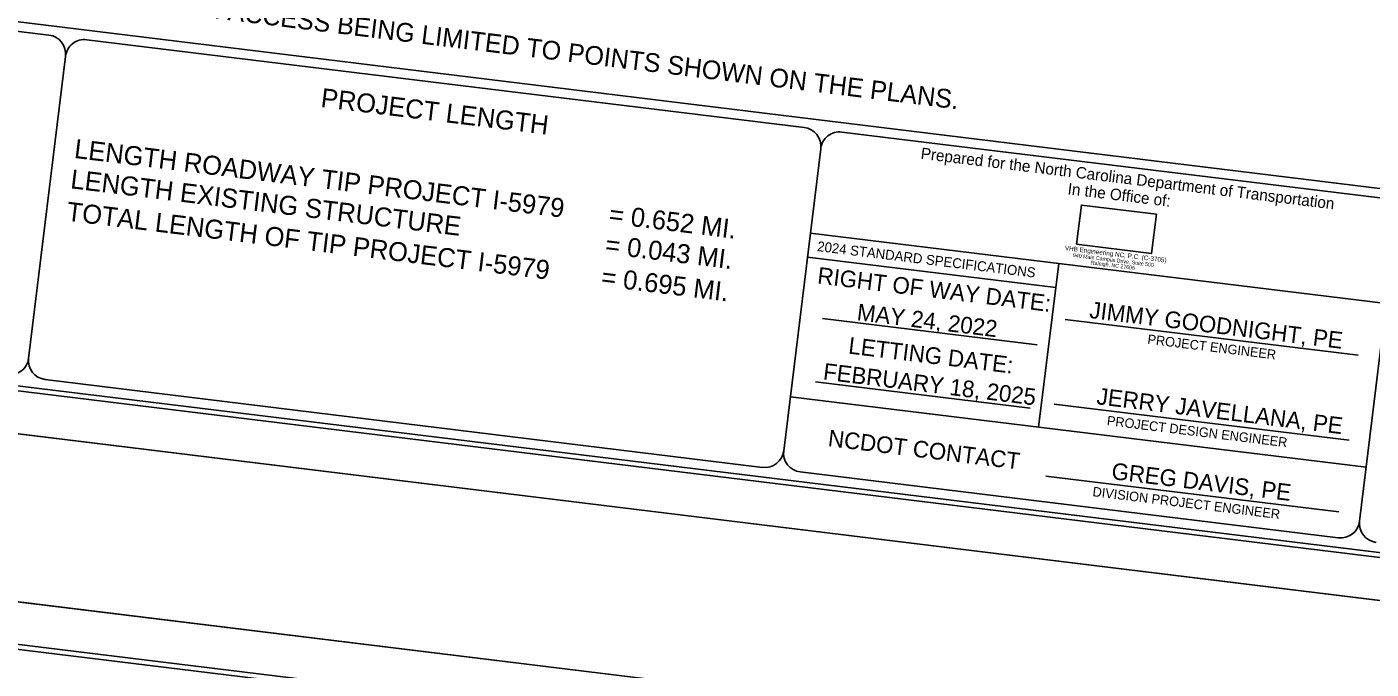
# Model space of a CAD drawing. Extents: x 1756435 to 1766932, y 416863 to 426859.
# Drawn here: x 1761555 to 1764409, y 421675 to 423038 of the extents above; entities that cross this region are included whole.
import ezdxf

# ---------------------------------------------------------------- set-up
doc = ezdxf.new("R2010")
doc.units = 0
for name, color, linetype in [('Default', 7, 'Continuous'), ('Old_Level_38', 7, 'Continuous'), ('Scratch_Level_2', 7, 'Continuous'), ('Sheet Cutting Line CELL', 7, 'Continuous'), ('Sheet Data Field CELL', 7, 'Continuous'), ('Sheet Plot Border Inside CELL', 7, 'Continuous'), ('Sheet Plot Border Outside CELL', 7, 'Continuous'), ('Sheet Symbology CELL', 7, 'Continuous'), ('Sheet Title CELL', 7, 'Continuous')]:
    doc.layers.add(name, color=color, linetype=linetype)

msp = doc.modelspace()

# ---------------------------------------------------------------- linework, layer by layer
at = {"layer": 'Default'}
msp.add_lwpolyline([(1763784, 422576.7), (1763943.2, 422557.2), (1763953.4, 422640.4), (1763794.2, 422659.9)], close=True, dxfattribs=at)
at = {"layer": 'Scratch_Level_2'}
msp.add_lwpolyline([(1759243.8, 422098.1), (1765929.9, 421280), (1765395.5, 416912.5), (1758709.3, 417730.7)], close=True, dxfattribs=at)
at = {"layer": 'Sheet Cutting Line CELL'}
for p, q in [((1759286.8, 422449.7), (1766036.5, 421623.8)), ((1765993.4, 421272.2), (1759243.8, 422098.1)), ((1765929.9, 421280), (1759243.8, 422098.1))]:
    msp.add_line(p, q, dxfattribs=at)
at = {"layer": 'Sheet Plot Border Inside CELL'}
for points in [[(1759349.9, 422533.3), (1766029.4, 421715.9), (1766546.9, 425944.9), (1759867.4, 426762.2)], [(1758771.9, 417813.5), (1765388.5, 417003.9), (1765901.1, 421193), (1759284.5, 422002.7)]]:
    msp.add_lwpolyline(points, close=True, dxfattribs=at)
at = {"layer": 'Sheet Plot Border Outside CELL'}
for points in [[(1766576, 426032.6), (1759826.3, 426858.6), (1759286.8, 422449.7), (1766036.5, 421623.8)], [(1758709.3, 417730.7), (1765395.5, 416912.5), (1765929.9, 421280), (1759243.8, 422098.1)]]:
    msp.add_lwpolyline(points, close=True, dxfattribs=at)
at = {"layer": 'Sheet Symbology CELL'}
msp.add_lwpolyline([(1765850.3, 421189), (1759894.7, 421917.7), (1759385, 417752.9), (1765340.6, 417024.1)], close=True, dxfattribs=at)
at = {"layer": 'Sheet Title CELL'}
for p, q in [((1760322.1, 423197.7), (1766013.7, 422501.2)), ((1761021.1, 423091.8), (1761602.3, 423020.7)), ((1761682.4, 423010.8), (1763205.5, 422824.5)), ((1761637.5, 422975.7), (1761559, 422334.4)), ((1763285.7, 422814.9), (1764428, 422675.1)), ((1763240.7, 422779.5), (1763162.2, 422138.2)), ((1764384.7, 421988.6), (1764463.2, 422629.9)), ((1764441.3, 422450.7), (1763218.8, 422600.3)), ((1763739.8, 422484.7), (1763212.5, 422549.2)), ((1763746.1, 422535.8), (1763703.5, 422188.3)), ((1763587.9, 422503.3), (1763587.9, 422503.3)), ((1763700.6, 422363.5), (1763244.6, 422419.3)), ((1763759.6, 422417.3), (1764381.5, 422341.1)), ((1763472.5, 422391.4), (1763472.5, 422391.4)), ((1763685.7, 422228.8), (1763229.8, 422284.6)), ((1764398.7, 422103.2), (1763176.3, 422252.9)), ((1763736.2, 422237.1), (1764362.4, 422160.5)), ((1763718.9, 422084.7), (1764340.8, 422008.6))]:
    msp.add_line(p, q, dxfattribs=at)
for points in [[(1760008.5, 422463.1), (1765940.5, 421737.2)], [(1761594.2, 422289.4), (1763117.2, 422103)], [(1763197.4, 422093.4), (1764339.7, 421953.6)]]:
    msp.add_lwpolyline(points, dxfattribs=at)
for centre, start, end in [((1761597.4, 422980.8), 353.0234, 83.0234), ((1761677.6, 422971), 83.0234, 173.0234), ((1763200.7, 422784.6), 353.0234, 83.0234), ((1763280.8, 422774.8), 83.0234, 173.0234), ((1761518.9, 422339.5), 263.0234, 353.0234), ((1761599.1, 422329.7), 173.0234, 263.0234), ((1763122.2, 422143.3), 263.0234, 353.0234), ((1763202.3, 422133.5), 173.0234, 263.0234), ((1764344.7, 421993.7), 263.0234, 353.0234), ((1764424.8, 421983.9), 173.0234, 263.0234)]:
    msp.add_arc(centre, 40.4, start, end, dxfattribs=at)

# ---------------------------------------------------------------- texts
at = {"layer": 'Default'}
for s, height, p in [('VHB Engineering NC, P.C. (C-3705)', 9.771, (1763758.7, 422564.3)), ('940 Main Campus Drive, Suite 500', 8.075, (1763776, 422549.9)), ('Raleigh, NC 27606', 8.075, (1763813.9, 422533.9))]:
    msp.add_text(s, height=height, rotation=352.9846, dxfattribs=at).set_placement(p)
at = {"layer": 'Old_Level_38'}
for s, p in [('LENGTH ROADWAY TIP PROJECT I-5979', (1761654.5, 422760.2)), ('LENGTH EXISTING STRUCTURE', (1761646.6, 422695.8)), ('TOTAL LENGTH OF TIP PROJECT I-5979', (1761638.2, 422627)), ('= 0.652 MI.', (1762789.5, 422621.3)), ('= 0.043 MI.', (1762781.6, 422556.9)), ('= 0.695 MI.', (1762773.2, 422488.2))]:
    msp.add_text(s, height=40.38, rotation=353.0234, dxfattribs=at).set_placement(p)
at = {"layer": 'Sheet Data Field CELL'}
for s, height, p in [('THIS IS A PARTIAL CONTROLLED ACCESS PROJECT WITH ACCESS BEING LIMITED TO POINTS SHOWN ON THE PLANS.', 39.75, (1760479.7, 423236.6)), ('MAY 24, 2022', 35.333, (1763316.3, 422415.7)), ('JIMMY GOODNIGHT, PE', 35.333, (1763810, 422420.4)), ('FEBRUARY 18, 2025', 35.333, (1763244.6, 422289.7)), ('JERRY JAVELLANA, PE', 35.333, (1763825.4, 422237.3)), ('GREG DAVIS, PE', 35.333, (1763856.7, 422078.3))]:
    msp.add_text(s, height=height, rotation=353.0234, dxfattribs=at).set_placement(p)
at = {"layer": 'Sheet Title CELL'}
for s, height, p in [('PROJECT LENGTH', 40.378, (1762178, 422868.3)), ('Prepared for the North Carolina Department of Transportation', 24.228, (1763452.2, 422758.2)), ('In the Office of:', 24.228, (1763764.1, 422683)), ('2024 STANDARD SPECIFICATIONS', 20.998, (1763232.4, 422562.5)), ('RIGHT OF WAY DATE: ', 35.332, (1763232.4, 422493.6)), ('LETTING DATE:', 35.332, (1763298.2, 422344.8)), ('PROJECT ENGINEER', 20.188, (1763933.7, 422365.5)), ('PROJECT DESIGN ENGINEER', 20.188, (1763847.5, 422192.7)), ('NCDOT CONTACT', 35.332, (1763254.9, 422148.2)), ('DIVISION PROJECT ENGINEER', 20.188, (1763817.1, 422042))]:
    msp.add_text(s, height=height, rotation=353.0234, dxfattribs=at).set_placement(p)

doc.saveas('drawing.dxf')
